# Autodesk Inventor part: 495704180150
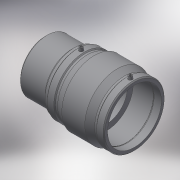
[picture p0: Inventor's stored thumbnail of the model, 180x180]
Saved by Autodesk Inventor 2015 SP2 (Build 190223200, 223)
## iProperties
Created: 2017-06
Part Number: 495704180150
Material: Generic
Description: PLASSON PE CAST IRON SPIGOT COUPLER TRANSITION 180-150
Document SubType Name: Modeling
Designer: KIM
Mass: 55.0731 g
Surface Area: 148.067 cm^2
Volume: 55.0731 cm^3
Density: 1 g/cm^3
Appearance: Default
Author: KIM
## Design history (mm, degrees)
derived "495704.ipt"
feature "Solid1::495704.ipt"
tag "TaggingFeature1"
body "Solid1"
other parameters: "d13" = 212, "d14" = 17.6296, "d15" = 104, "d16" = 104, "d17" = 171, "d19" = 3.52592, "d20" = 168 deg, "d22" = 204.92, "d23" = 218, "d24" = 198.7724, "d25" = 135 deg, "d26" = 84.8, "d27" = 135 deg, "d29" = 114, "d35" = 15, "d39" = 5 deg, "d45" = 4, "d46" = 14, "d47" = 0, "d50" = 3, "d51" = 0, "d52" = 30.16, "d53" = 7.54, "d55" = 0.1, "d56" = 187, "d57" = 103, "d58" = 127, "d62" = 5.1, "d65" = 8.5, "L_" = 339, "L_1" = 104, "D_1" = 218, "A_" = 114, "d_2" = 12, "L_2" = 127, "H_" = 103
